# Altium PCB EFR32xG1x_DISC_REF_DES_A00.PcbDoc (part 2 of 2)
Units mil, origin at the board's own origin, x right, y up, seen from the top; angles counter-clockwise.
Board outline 1181.1 x 1771.65 mil, 4 copper layers (Top Layer, Signal Layer 2, Signal Layer 3, Bottom Layer), stack 63.229 mil thick; 88 components, 86 nets, 332 pads, 389 vias.
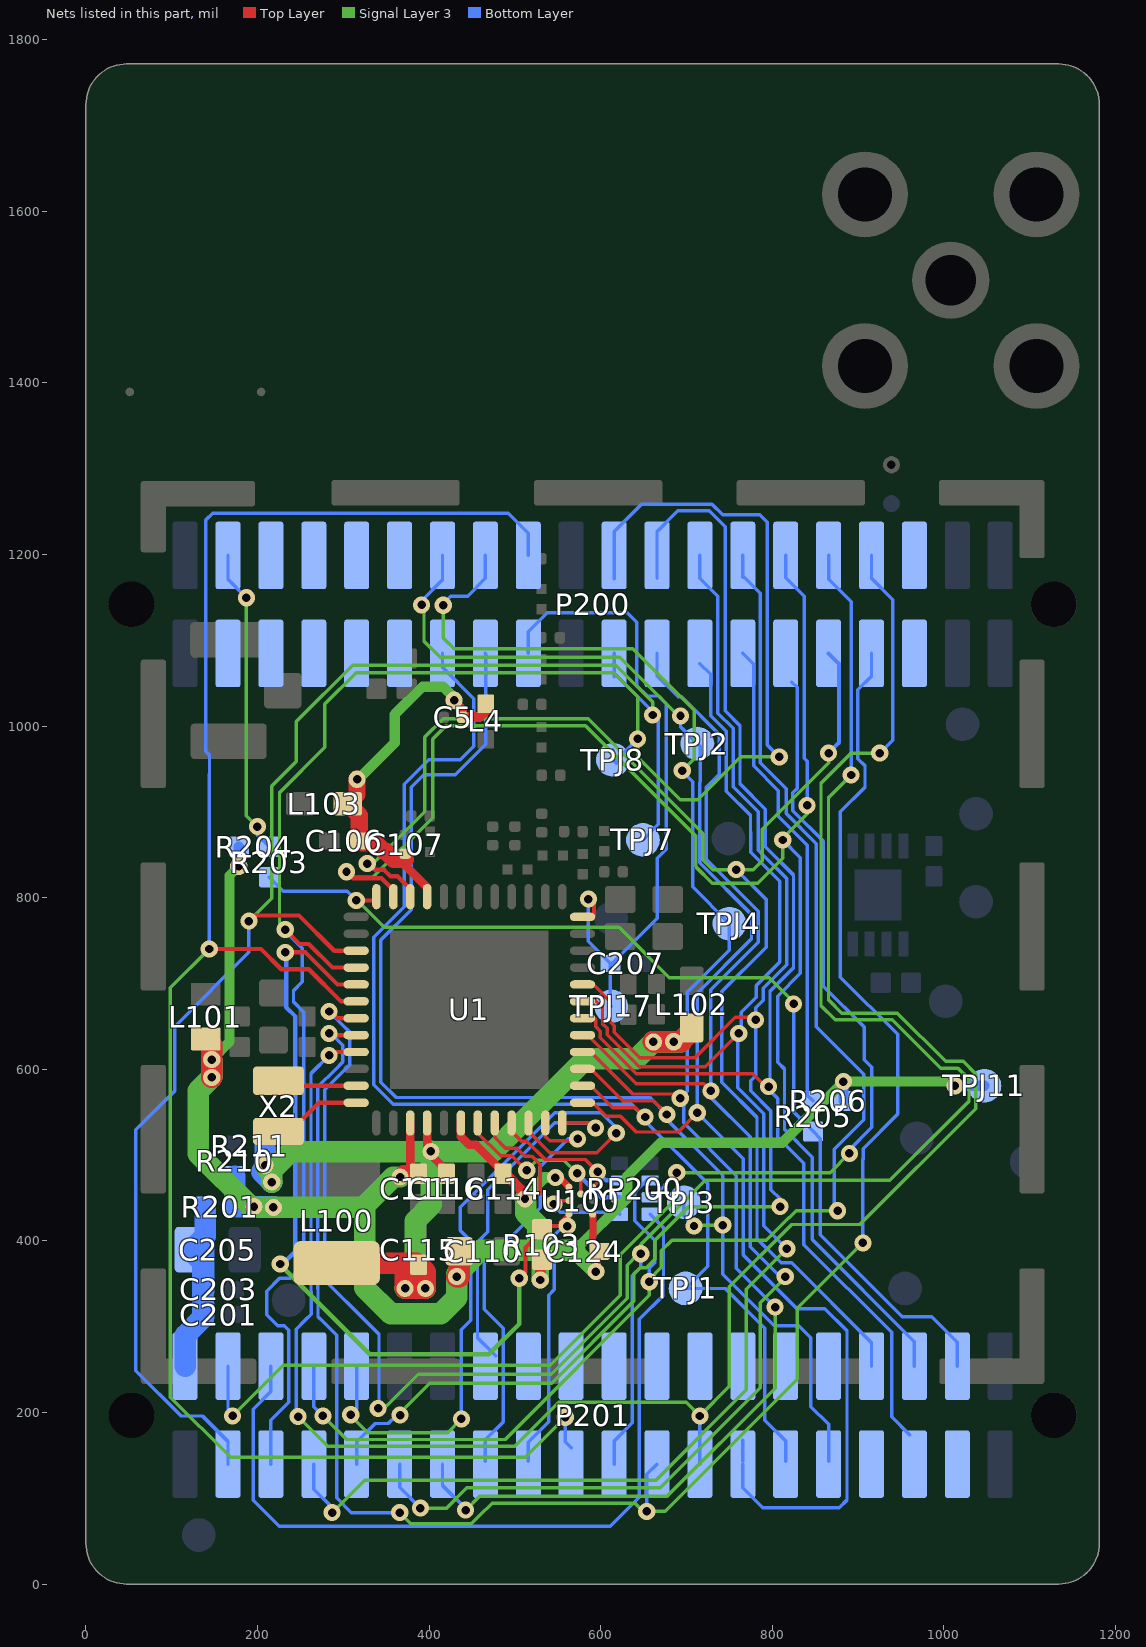
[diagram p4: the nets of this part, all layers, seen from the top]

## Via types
v1: diameter 20, hole 9.84, Top Layer to Bottom Layer, tented both sides, 385 vias
v2: diameter 19.68, hole 9.84, Top Layer to Bottom Layer, tented both sides, 2 vias
v3: diameter 20, hole 9.84, Top Layer to Bottom Layer, 2 vias

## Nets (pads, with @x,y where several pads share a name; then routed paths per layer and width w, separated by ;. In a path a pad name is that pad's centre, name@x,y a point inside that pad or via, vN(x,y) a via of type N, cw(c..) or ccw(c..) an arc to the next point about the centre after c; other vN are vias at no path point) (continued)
RADIO_PA2: P200.21 P201.3 TPJ7.1 U1.27 | length 1872.5
  Top Layer w5: v1(189.96,772.64) 196.62,779.3 248.26,779.3 289.37,738.19 U1.27@314.96,738.19
  Signal Layer 3 w4: v1(189.96,772.64) 216.54,799.21 216.54,930.12 245.08,958.66 245.08,1005.27 310.81,1071 617.48,1071 660.47,1028.01 v1(660.47,1012.84)
  Bottom Layer w4: P201.3@165.55,139.76 165.55,166.14 135.83,195.87 110.94,195.87 58.07,248.73 58.07,529.33 103.35,574.6 103.35,649.61 189.96,736.22 v1(189.96,772.64) ; P200.21@615.55,1057.68 P200.21@615.55,1061.61 ; P200.21@615.55,1084.65 P200.21@615.55,1061.61 ; TPJ7.1@649.21,867.32 657.73,875.84 657.48,876.1 667,885.62 667,1006.31 v1(660.47,1012.84) 660.47,1016.7 P200.21@615.55,1061.61
RADIO_PA3: P200.22 P201.5 TPJ8.1 U1.28 | length 2331
  Top Layer w5: v1(232.28,762.8) 249.02,746.06 259.76,746.06 287.32,718.5 U1.28@314.96,718.5
  Signal Layer 3 w4: v1(232.28,762.8) 225.59,769.48 225.59,922.44 278.54,975.39 278.54,1025.69 314.86,1062 615.17,1062 643,1034.17 v1(643,985) 643,963.69 692.69,914 713,914 763,964 v1(808,964)
  Bottom Layer w4: P201.5@215.55,139.76 215.55,191.13 236.12,211.7 236.12,287.4 ; v1@235.24,757.86 252.22,740.88 252.22,702.01 241.87,691.67 241.87,678.41 253.94,666.35 253.94,372.05 238.28,356.39 225.58,356.39 210.54,341.35 210.54,314.07 223.33,301.28 230.9,301.28 236.22,295.95 236.22,287.4 ; TPJ8.1@614.17,972.44 TPJ8.1@614.17,960.63 618.36,956.45 618.36,960.36 v1(643,985) ; P200.22@615.55,1171.85 P200.22@615.55,1198.82 615.55,1226.77 647.51,1258.73 729.64,1258.73 742.21,1246.16 785.34,1246.16 794.12,1237.38 794.12,977.88 v1(808,964)
RADIO_PA4: P201.17 R103.2 U1.29 U100.A3 | length 1280.2
  Top Layer w5: v1(232.28,736.22) 255.83,736.22 293.23,698.82 U1.29@314.96,698.82 ; v1(504.95,356.32) 512.41,363.78 512.41,392.33 531.5,411.42 R103.2@531.5,413.39 535.3,417.19 v1@557.14,417.19 ; v1(560.93,417.19) v1@557.14,417.19 ; U100.A3@562.91,431.1 553.07,421.26 v1@557.14,417.19
  Signal Layer 3 w5: v1(226.38,373.03) 226.38,372.05 330.71,267.72 469.5,267.72 504.95,303.16 v1(504.95,356.32)
  Bottom Layer w4: P201.17@515.55,143.11 515.55,165.16 539.37,188.98 539.37,253.47 ; 539.17,253.66 539.37,253.47 ; v1(560.93,417.19) 556.88,417.19 546.04,406.35 546.04,343.28 539.37,336.61 539.37,253.47
  Bottom Layer w5: v1@227.36,371.06 227.85,371.56 244.09,387.8 244.09,661.42 233.37,672.14 233.37,734.36 233.3,734.29 232.28,735.31 v1(232.28,736.22)
RADIO_PA5: P200.18 P201.19 U1.30 | length 2200.8
  Top Layer w5: v1(143.7,740.16) 204.07,740.16 227.7,716.54 259.76,716.54 297.17,679.13 U1.30@314.96,679.13
  Signal Layer 3 w4: v1(143.7,740.16) 98.43,694.88 98.43,217.85 168.63,147.64 511.81,147.64 v1(558.58,194.41)
  Bottom Layer w4: v1(143.7,740.16) 143.7,943.91 143.95,944.16 143.95,966.28 139.76,970.47 139.76,1240.16 147.64,1248.03 492.13,1248.03 515.55,1224.61 P200.18@515.55,1198.82 ; v1(558.58,194.41) 558.58,165.95 P201.19@565.55,158.98
RADIO_PB11: P200.34 P201.21 U1.31 | length 2490.7
  Top Layer w5: v1(283.39,667.32) 285.36,667.32 293.23,659.45 U1.31@314.96,659.45
  Signal Layer 3 w4: v1@344,201.28 387.3,244.59 542.08,244.59 630.78,333.29 630.78,371.78 643.86,384.86 v1(646.69,384.86) 646.69,395.7 721.54,470.55 937.01,470.55 1029.15,562.69 1029.15,588.58 1016.35,601.38 996.05,601.38 939.95,657.48 873.07,657.48 856.66,673.89 856.66,933.51 891.65,968.5 v1(925.2,968.5)
  Bottom Layer w4: v1(283.39,667.32) 299.39,651.32 299.47,651.32 307.39,643.4 307.39,605.13 278.54,576.28 278.54,354.24 303.6,329.18 303.69,329.18 341.54,291.34 341.54,205.71 v1(340.55,204.72) ; P201.21@615.55,139.76 615.55,166.73 636.81,187.99 636.81,359.25 646.69,369.13 v1(646.69,384.86) ; P200.34@915.55,1198.82 915.55,1172.09 940.21,1147.43 940.21,983.52 v1(925.2,968.5)
RADIO_PB12: P200.33 P201.23 U1.32 | length 2239.1
  Top Layer w5: v1(283.39,641.73) 285.35,639.76 U1.32@314.96,639.76
  Signal Layer 3 w4: v1(365.67,83.19) 378.68,70.14 449.08,70.14 453.74,74.8 458.44,79.51 473.3,94.36 639.89,94.36 653.54,80.71 v1(653.54,84.65) 675.2,84.65 829.23,238.68 829.23,321.36 v1(905.51,397.64)
  Bottom Layer w4: v1(283.39,641.73) v1@284.41,640.71 ; v1@285.43,641.73 285.61,641.73 299.39,627.95 299.39,608.44 291,600.05 270.29,579.35 270.29,344.39 270.42,344.26 270.42,311.76 277.3,304.87 292.19,289.98 292.19,100.44 309.44,83.19 v1(365.67,83.19) ; v1(653.54,84.65) 653.54,127.75 P201.23@665.55,139.76 ; v1(905.51,397.64) 905.51,495.09 905.76,495.34 905.76,507.56 946,547.79 946,640.61 879.2,707.42 879.2,899.86 907.99,928.65 907.99,953.74 899.73,962 899.73,1042.45 915.55,1058.27 P200.33@915.55,1084.65
RADIO_PB13: P200.32 P201.25 U1.33 | length 2362.4
  Top Layer w5: v1(283.39,616.14) 283.39,618.11 281.42,620.08 U1.33@314.96,620.08
  Signal Layer 3 w4: v1(247.31,195.1) 281.97,160.44 499.61,160.44 551.18,212.01 699.41,212.01 v1(715.55,195.87) 750,230.31 750,346.45 822.59,419.04 902.06,419.04 1037.15,554.13 1037.15,594.49 1022.26,609.38 1001.85,609.38 945.75,665.48 880.87,665.48 865.43,680.93 865.43,916.61 v1(891.73,942.91)
  Bottom Layer w4: v1@244.98,200.24 244.98,297.15 255.85,308.02 262.39,314.56 262.39,340.97 262.29,341.08 262.29,595.05 v1(283.39,616.14) ; P201.25@715.55,139.76 v1(715.55,195.87) ; P200.32@865.55,1198.82 865.55,1170.91 891.73,1144.73 v1(891.73,942.91)
RADIO_PB14: U1.35 X2.2 | length 93
  Top Layer w5: X2.2@224.33,586.61 230.24,580.71 U1.35@314.96,580.71
RADIO_PB15: U1.36 X2.1 | length 104.4
  Top Layer w5: X2.1@224.33,527.56 238.11,527.56 271.57,561.02 U1.36@314.96,561.02
RADIO_PC6: RP200.2 U1.43 U100.D2 | length 243.9
  Top Layer w4: U1.43@456.61,537.4 456.61,525.59 483.2,499 496.44,499 513.16,482.28 v1(513.7,482.28) ; v1(572.38,478.78) 576.69,474.46 U100.D2@576.69,454.72
  Signal Layer 3 w4: v1(513.7,482.28) 525.51,494.09 557.06,494.09 v1(572.38,478.78)
  Bottom Layer w5: v1(572.38,478.78) 600.37,450.79 RP200.2@622.05,450.79
RADIO_PC7: RP200.1 U1.44 U100.C3 | length 228.3
  Top Layer w4: U1.44@476.38,537.4 476.3,520.7 489,508 502,508 511.65,498.35 517.82,498.35 517.88,498.28 520.33,498.28 529.7,488.91 529.7,475.66 529.45,475.4 529.45,456.69 v1@537.32,448.82 ; v1(545.28,442.91) 549.21,446.85 U100.C3@562.91,446.85
  Bottom Layer w4: v1@544.25,441.89 552.95,433.19 619.96,433.19 RP200.1@622.05,431.1
RADIO_PC8: RP200.3 U1.45 U100.E1 | length 179.7
  Top Layer w4: U1.45@496.06,537.4 495.98,527.64 507.62,516 513.92,516 535.15,494.78 581.91,494.78 v1(596.38,480.31) 596.38,468.5 U100.E1@590.47,462.6
  Bottom Layer w5: v1(596.38,480.31) 606.22,470.47 RP200.3@622.05,470.47
RADIO_PC9: P201.10 U1.46 | length 831
  Top Layer w4: U1.46@515.75,537.4 515.75,527.56 540.53,502.78 595.22,502.78 v1(618.03,525.59)
  Signal Layer 3 w4: v1(308.58,197.36) 308.58,196.39 328.53,176.44 421.52,176.44 v1(437.52,192.44)
  Bottom Layer w4: v1(308.58,197.36) 315.55,204.33 P201.10@315.55,253.94 ; v1@437.52,194.26 437.52,296.58 448.32,307.38 448.32,400.11 436.38,412.05 436.38,439.33 546.26,549.21 600.39,549.21 618.03,531.57 v1(618.03,525.59)
RADIO_PC10: P201.15 U1.47 | length 501
  Top Layer w4: U1.47@535.43,537.4 535.43,521.57 540.36,516.64 570.88,516.64 v1(573.02,518.78)
  Bottom Layer w4: P201.15@465.55,143.11 465.55,168.31 486.12,188.87 486.12,298.33 464.32,320.13 464.32,373.76 529.28,438.72 529.28,475.23 529.7,475.66 529.7,486.39 562.09,518.78 v1(573.02,518.78)
RADIO_PC11: P201.16 U1.48 | length 409
  Top Layer w4: U1.48@555.04,537.4 U1.48@555.12,537.4 588.34,537.4 v1(594.03,531.71)
  Bottom Layer w4: P201.16@477.61,265.99 456.32,287.28 456.32,398.24 468.5,410.43 468.5,459.71 546.19,537.4 588.34,537.4 v1(594.03,531.71)
RADIO_PD13: P200.31 P201.34 U1.22 | length 1725.3
  Top Layer w5: v1(327.77,839.61) 329.62,839.61 336.88,832.35 347.53,832.35 354.87,825 363.03,825 377.87,810.16 U1.22@377.87,801.18
  Signal Layer 3 w4: v1(327.77,839.61) 334.47,839.61 395,900.14 395,987.21 416.29,1008.5 585.49,1008.5 719,875 719,844.41 730.73,832.68 v1(757.87,832.68) 777.6,832.68 788,843.08 788,879.66 865.55,957.21 v1(865.55,968.5)
  Bottom Layer w4: v1(757.87,832.68) 792.68,797.87 792.68,742.13 741.14,690.59 741.14,584.75 782.13,543.76 782.13,402.42 810.27,374.27 822.58,374.27 915.55,281.3 P201.34@915.55,253.94
  Bottom Layer w5: v1(865.55,968.5) 877.72,980.67 877.72,1072.48 P200.31@865.55,1084.65
RADIO_PD14: P200.30 P201.36 U1.23 | length 1893.4
  Top Layer w5: v1(303.68,830.18) 311.25,822.61 344.39,822.61 358.19,808.81 U1.23@358.27,801.18
  Signal Layer 3 w4: v1(303.68,830.18) 303.55,830.18 303.15,829.78 309.32,823.61 334.4,823.61 404,893.21 404,984.9 419.61,1000.5 582.18,1000.5 711,871.68 711,835.73 730.05,816.68 782.86,816.68 812.05,845.86 v1(812.05,867.17) 812.05,869.13 840.55,897.64 v1(840.55,907.48)
  Bottom Layer w4: v1(812.05,867.17) 832.68,846.54 832.68,711.76 806.1,685.18 806.1,608.27 814.13,600.24 814.13,529.88 846.46,497.55 846.46,401.57 965.55,282.48 P201.36@965.55,253.94 ; P200.30@815.55,1198.82 815.55,1172.9 836.98,1151.47 836.98,998.16 836.99,962.7 840.55,959.14 v1(840.55,907.48)
RADIO_PD15: P201.38 R203.1 R205.1 U1.24 | length 1220.3
  Top Layer w5: v1(314.96,796.78) 334.1,796.78 U1.24@338.5,801.18
  Signal Layer 3 w4: v1(314.96,796.78) 316.12,796.78 347.57,765.33 621.24,765.33 679.94,706.63 796.32,706.63 824.8,678.15 v1(824.8,676.18)
  Bottom Layer w4: R203.1@213.58,823.82 230.06,807.34 304.4,807.34 v1(314.96,796.78) ; v1(824.8,676.18) 824.8,550.2 R205.1@847.44,527.56 855.85,519.15 855.85,407.03 951.35,311.54 985.75,311.54 1015.55,281.73 P201.38@1015.55,253.94
RADIO_PF0: P200.14 P201.27 TPJ2.1 U1.1 | length 1856.4
  Top Layer w4: U1.1@578.66,561.02 U1.1@578.74,561.02 590.47,561.02 606.22,545.28 623,545.28 641.44,526.84 690.14,526.84 v1(712.52,549.21)
  Signal Layer 3 w4: v1@390,1141 394,1137 394,1099 413,1080 622,1080 690.19,1011.81 v1(692.91,1011.81)
  Bottom Layer w4: v1(391.26,1141.26) 391.26,1146.18 415.55,1170.47 P200.14@415.55,1198.82 ; v1(692.91,1011.81) 692.91,999.21 TPJ2.1@712.6,979.53 715.8,976.32 715.8,934.85 715.13,934.18 715.13,841.48 715.8,840.81 715.8,840.21 775.69,780.32 775.69,751.97 712.35,688.63 712.35,549.39 v1(712.52,549.21) 766.13,495.6 766.13,383.48 828.74,320.87 861.31,320.87 886.98,295.19 886.98,97.95 878.13,89.1 788.9,89.1 765.55,112.44 P201.27@765.55,139.76 ; P201.27@765.55,143.11 P201.27@765.55,167.52
RADIO_PF1: P200.13 P201.29 TPJ1.1 U1.2 | length 1524.2
  Top Layer w4: U1.2@578.74,580.71 588.5,580.71 614.09,555.12 640.83,555.12 v1(651.61,544.33)
  Bottom Layer w4: P200.13@415.55,1084.65 415.55,1068.45 452,1032 452,976.33 436.17,960.5 399.48,960.5 371.06,932.09 371.06,789.37 335.63,753.94 335.63,581.69 358.27,559.06 635.83,559.06 v1@651.57,543.31 ; v1@651.5,543.31 651.5,539.97 724.66,466.8 724.66,370.33 TPJ1.1@698.82,344.49 745.13,344.49 791.34,298.28 791.34,190.94 815.55,166.73 P201.29@815.55,143.11
RADIO_PF2: P200.15 P201.31 TPJ3.1 U1.3 | length 1607.1
  Top Layer w4: U1.3@578.74,600.39 588.5,600.39 625.78,563.12 661.32,563.12 v1(677.16,547.24)
  Signal Layer 3 w4: v1(708.66,417.32) 709.8,418.46 709.96,418.31 v1(742.13,418.31)
  Bottom Layer w4: P200.15@465.55,1084.65 466,1084.2 466,979.01 430.28,943.29 393.58,943.29 379.06,928.77 379.06,786.06 343.63,750.62 343.63,585.01 361.58,567.06 657.35,567.06 659.45,564.96 v1(677.16,547.24) 677.16,541.35 742.13,476.39 v1(742.13,418.31) 742.13,361.23 802.08,301.28 830.9,301.28 844.98,287.19 844.98,206.6 865.55,186.03 P201.31@865.55,143.11 ; TPJ3.1@696.85,444.88 696.85,429.13 v1(708.66,417.32)
RADIO_PF3: P200.16 P201.13 TPJ4.1 U1.4 | length 1964.2
  Top Layer w4: U1.4@578.66,620.08 U1.4@578.74,620.08 588.5,620.08 637.46,571.12 687.65,571.12 v1(692.64,566.12)
  Signal Layer 3 w4: v1@416.36,1140.64 416.36,1102.64 429,1090 637.35,1090 708.91,1018.44 708.91,961.91 v1(695,948) ; v1(442.44,86.14) 458.66,102.36 677.17,102.36 803.15,228.34 v1(803.15,322.83)
  Bottom Layer w4: P201.13@415.55,139.76 415.55,114.89 442.44,88 v1(442.44,86.14) ; v1(416.36,1140.8) 416.36,1142.74 425.1,1151.48 444.79,1151.48 465.55,1172.24 P200.16@465.55,1198.82 ; v1(695,948) 695,947.36 707.13,935.22 707.13,812.55 TPJ4.1@750,769.68 750,738.92 701.04,689.96 701.04,574.52 v1(692.64,566.12) 696.52,562.25 696.52,537.4 758.13,475.79 758.13,367.86 v1(803.15,322.83)
RADIO_PF4: P200.23 P201.11 U1.5 | length 1687.3
  Top Layer w4: U1.5@578.66,639.76 U1.5@578.74,639.76 584.65,639.76 641.16,583.25 719.9,583.25 v1(728.35,574.8)
  Signal Layer 3 w4: v1(389.76,88.58) 420.28,88.58 443.9,112.2 669.29,112.2 785.69,228.61 785.69,328.01 815.95,358.27 v1(814.96,358.27)
  Bottom Layer w4: P201.11@365.55,139.76 365.55,112.8 v1(389.76,88.58) ; P200.23@665.55,1084.65 665.55,1058.86 690.19,1034.22 694.23,1034.22 738.28,990.17 738.28,943.68 723.13,928.53 723.13,844.79 783.69,784.24 783.69,748.03 728.35,692.69 v1(728.35,574.8) ; v1@728.52,574.8 728.52,566.93 774.13,521.32 774.13,393.2 809.06,358.27 v1(814.96,358.27)
RADIO_PF5: P200.24 P201.35 U1.6 | length 1579.2
  Top Layer w4: U1.6@582.68,661.42 590.58,661.42 594,658 594,649.79 599.5,644.29 599.5,636.72 641.53,594.69 777.35,594.69 792.27,579.78 v1(795.62,579.78)
  Bottom Layer w4: P200.24@665.55,1172.09 P200.24@665.55,1198.82 665.55,1226.57 689.71,1250.73 726.32,1250.73 744.98,1232.07 744.98,1017.8 762.28,1000.5 762.28,932.59 791.69,903.19 791.69,859.39 824.68,826.4 824.68,718.38 797.28,690.98 797.28,581.44 v1(795.62,579.78) 795.62,576.43 806.13,565.92 806.13,520.67 836.5,490.29 836.5,395.67 938.92,293.25 938.92,194.98 P201.35@960.16,173.74
RADIO_PF6: P200.25 P201.7 U1.7 | length 1801.9
  Top Layer w4: U1.7@578.66,679.13 U1.7@578.74,679.13 594.87,679.13 602,672 602,653.11 607.5,647.6 607.5,640.03 644.84,602.69 721.79,602.69 v1(760.83,641.73)
  Signal Layer 3 w4: v1(286.81,83.19) 324.69,121.06 664.37,121.06 769.69,226.38 769.69,343.5 v1(816.93,390.75)
  Bottom Layer w4: P201.7@265.55,139.76 265.55,110.43 286.81,89.17 v1(286.81,83.19) ; P200.25@715.55,1072.83 728.12,1060.27 728.12,1012.04 746.28,993.87 746.28,924.02 774.5,895.8 774.5,876.09 774.61,875.98 774.61,853.09 808.68,819.02 808.68,725.01 781.28,697.61 781.28,683.85 763.78,666.35 763.78,644.68 v1(760.83,641.73) 759.46,640.37 759.46,578.64 790.13,547.98 790.13,417.55 v1(816.93,390.75)
RADIO_PF7: P200.26 P201.9 U1.8 | length 1777.6
  Top Layer w4: v1@364.17,198.82 v1(366.14,196.85) ; U1.8@578.74,698.82 591.18,698.82 610,680 610,656.42 615.5,650.91 615.5,643.34 645.46,613.39 709.86,613.39 756.9,660.43 777.56,660.43 v1(780.51,657.48)
  Signal Layer 3 w4: v1(366.14,196.85) 366.14,199.63 400.77,234.25 543.06,234.25 638.78,329.98 638.78,361.69 645.95,368.86 653.31,368.86 662.69,378.23 662.69,400.39 702.26,439.96 v1(809.06,439.96)
  Bottom Layer w4: P201.9@315.55,139.76 315.55,165.69 336.96,187.1 352.46,187.1 362.2,196.85 v1(366.14,196.85) ; P200.26@715.55,1198.82 715.55,1172.28 736.47,1151.36 736.47,1015 754.28,997.19 754.28,929.27 783.69,899.87 783.69,855.33 816.68,822.34 816.68,721.69 789.28,694.3 789.28,680.54 780.51,671.77 v1(780.51,657.48) 780.51,592.52 774.61,586.61 774.61,574.81 798.13,551.29 798.13,459.75 809.06,448.82 v1(809.06,439.96)
USB_VBUS: P200.35
USB_VREG: P200.36
VBIAS: C5.1 C106.1 C107.1 L4.1 L103.2 U1.21 | length 436.9
  Top Layer w8: C5.1@438,1010.65 C5.1@438.65,1010 C5.1@438.82,1010.17 ; C5.1@439,1010 439.17,1010.17 C5.1@439.64,1010.64
  Top Layer w10: 369.55,840.02 397.56,812.01 U1.21@397.56,801.18
  Top Layer w12: v1(429,1030) 429,1028 438,1019 C5.1@438,1010.65 ; C5.1@438.82,1010.17 C5.1@439.17,1010.17 ; C5.1@439.64,1010.64 458.64,1010.64 466,1018 L4.1@466,1026
  Top Layer w20: v1(315.94,937.99) 315.94,920.28 L103.2@305.12,909.45 318.52,896.05 318.52,866.52 C106.1@318.9,866.14 321.43,863.61 337.71,863.61 347.21,854.11 349.1,854.11 358.72,844.49 372.05,844.49
  Signal Layer 3 w12: v1@317.57,937.98 360,980.4 360,1013.54 392.23,1045.77 416.23,1045.77 v1@428,1034
VDCDC: C115.1 C116.1 L100.2 L102.1 R211.2 U1.40 | length 1146.8
  Top Layer w10: U1.40@397.56,537.4 v1@397.56,504.78 ; v1(401.96,504.16) 401.34,504.78 v1@397.56,504.78 ; C116.1@420.28,478.35 420.28,482.06 v1@397.56,504.78
  Top Layer w25: L100.2@291.26,374.02 C115.1@385.75,374.02 ; v1(661.42,631.89) v1@693,631.89 ; v1(685,632) 692.95,632 706,645.05 L102.1@706,648 ; C115.1@385.75,374.02 395.59,364.17 v1(395.59,344.49) v1(371.97,344.49) 371.97,360.24 C115.1@385.75,374.02
  Signal Layer 3 w25: v1(208.72,488.19) v1@216.54,476.38 ; v1(216.54,468.5) v1@216.54,476.38 ; v1@393.82,346.26 383.78,356.3 ; v1(395.59,344.49) v1(371.97,344.49) 383.78,356.3 ; v1@402.56,504.16 v1@402.56,503.94 ; v1@694.04,631.89 v1(661.42,631.89) 641.73,612.2 582.6,612.2 509.76,539.37 474.33,503.94 v1@402.56,503.94 ; v1@216.54,476.38 216.54,482.28 238.19,503.94 v1@402.56,503.94 ; 383.78,356.3 383.78,423.15 402.56,441.93 v1@402.56,503.94
  Bottom Layer w25: R211.2@208.66,510.83 208.72,506.89 v1(208.72,488.19) 204.72,480.31 v1(216.54,468.5)
VMCU: C110.1 C111.1 C114.1 C124.1 L101.1 R103.1 R201.2 R204.1 R206.1 R210.2 TPJ11.1 U1.39 U1.42 U100.A1 U100.E3 | length 2324.7
  Top Layer w8: v1(547.17,473.78) 551.73,473.78 U100.E3@562.91,462.6 ; U100.A1@590.47,431.1 590.93,430.65 590.93,404.76 590.47,404.31 590.47,391.73 C124.1@594.41,387.8
  Top Layer w10: U1.39@377.87,537.4 377.87,488.19 C111.1@387.72,478.35 ; U1.42@436.93,537.4 436.93,521.65 446.77,511.81 454.65,511.81 C114.1@486.14,480.31
  Top Layer w12: C114.1@486.14,480.31 511.73,454.73 v1(511.73,448.82) ; v1(529.53,354.33) 529.53,375.98 R103.1@531.5,377.95 ; v1(594.41,364.17) C124.1@594.41,387.8
  Top Layer w20: v1(366.06,474.41) 370,478.35 C111.1@387.72,478.35
  Top Layer w25: L101.1@139.76,635.24 146.65,628.35 v1(146.65,611.22) v1(146.65,590.55) ; v1(432.11,358.29) 435.02,358.29 C110.1@435.04,387.8
  Signal Layer 3 w12: v1(146.65,611.22) 167.32,631.89 167.32,825.79 v1(178.15,836.61) ; 527.56,388.78 529.53,386.81 ; 569.8,388.78 630.89,449.86 630.89,475.37 669.73,514.22 811.46,514.22 v1(882.87,585.63) 1007.87,585.63 v1(1012.8,580.71)
  Signal Layer 3 w13: v1(511.73,448.82) 511.73,451.32 534.19,473.78 v1(547.17,473.78)
  Signal Layer 3 w20: v1(529.53,354.33) 529.53,386.81 ; 569.8,388.78 v1(594.41,364.17)
  Signal Layer 3 w25: v1(146.65,611.22) v1(146.65,590.55) 130.91,574.8 130.91,501.31 192.26,439.96 v1(195.87,439.96) 196.85,438.98 v1(218.5,438.98) 322.68,438.98 324.72,441.02 ; v1(366.06,474.41) 358.11,474.41 324.72,441.02 ; v1(511.73,448.82) 512.64,447.91 512.64,432.16 526.57,418.23 526.57,402.41 527.56,401.42 527.56,388.78 ; 569.8,388.78 527.56,388.78 ; 324.72,441.02 324.72,345.47 355.24,314.96 413.39,314.96 432.11,333.68 v1(432.11,358.29) 432.11,361.24 459.65,388.78 527.56,388.78
  Bottom Layer w12: v1(178.15,836.61) R204.1@178.15,859.25 ; R206.1@882.87,562.99 v1(882.87,585.63) ; v1(1012.8,580.71) TPJ11.1@1047.24,580.71
  Bottom Layer w25: R210.2@173.23,475.39 173.23,440.94 R201.2@174.21,439.96 v1(195.87,439.96) ; v1@199.73,439.96 v1(195.87,439.96) ; v1(218.5,438.98) 217.98,439.5 195.87,439.5 v1(195.87,439.96)
VMCU_IN: C201.1 C203.1 C205.1 P201.2 R201.1 | length 285.6
  Bottom Layer w25: P201.2@115.55,253.94 115.55,289.76 C201.1@137.32,311.54 ; 137.32,325.79 C201.1@137.32,311.54 ; C205.1@137.8,403.54 137.32,403.07 137.32,342.05 C203.1@136.34,341.06 ; R201.1@138.78,439.96 138.78,405.51 122.05,388.78 136.34,374.49 C203.1@136.34,341.06 ; C203.1@136.34,341.06 136.34,312.52 C201.1@137.32,311.54
WSTK_F4: C207.1 P200.17 TPJ17.1 U1.12 | length 785.8
  Top Layer w5: U1.12@578.66,777.56 U1.12@578.74,777.64 ; U1.12@578.74,777.56 591.56,777.56 592,778 592,791.93 v1(585.66,798.27)
  Bottom Layer w4: P200.17@515.55,1084.65 515.55,1110.04 537.5,1131.98 630.9,1131.98 642.11,1120.77 642.11,1046.87 653.98,1035 667.51,1035 676.47,1026.04 676.47,856.17 665.96,845.66 665.96,776.2 613.19,723.43 C207.1@611.22,723.43 ; v1(585.66,798.27) 585.66,748.99 C207.1@611.22,723.43 ; TPJ17.1@612.2,673.23 611.22,674.21 C207.1@611.22,723.43
WSTK_F14: P200.27 R205.2 R206.2 | length 555.6
  Bottom Layer w4: P200.27@765.55,1084.65 778.12,1072.08 778.12,953.68 807.09,924.71 807.09,894.76 840.68,861.17 840.68,685.17 840.8,685.04 840.8,569.63 R205.2@847.44,562.99
WSTK_F15: P200.28 P201.8 RP200.6 | length 1785.7
  Signal Layer 3 w4: v1(276.19,196.01) 303.76,168.44 488.56,168.44 656.53,336.41 v1(656.53,352.38) 656.53,354.87 670.69,369.03 670.69,388.2 683.07,400.59 792.82,400.59 819.27,427.04 819.75,427.04 827.75,435.04 v1(875.98,435.04)
  Bottom Layer w4: P201.8@265.55,253.94 265.55,206.65 v1(276.19,196.01) ; v1(656.53,352.38) 656.53,368.14 662.69,374.3 662.69,400.62 639.76,423.54 639.76,456.61 653.62,470.47 RP200.6@657.48,470.47 ; P200.28@765.55,1173.47 P200.28@765.55,1175.39 ; P200.28@765.55,1198.82 P200.28@765.55,1175.39 ; v1(875.98,435.04) 872.05,438.97 872.05,506.88 906.5,541.33 906.5,594.36 851.38,649.48 851.38,862.71 816.01,898.08 816.01,927.1 786.12,956.99 786.12,1154.83 P200.28@765.55,1175.39
WSTK_F16: P200.29 P201.4 RP200.7 | length 1597.5
  Signal Layer 3 w4: v1(170.87,196.01) 230.05,255.19 541.37,255.19 622.78,336.6 622.78,383.58 688.61,449.42 v1(688.61,479.49) 867.29,479.49 v1(889.76,501.97)
  Bottom Layer w4: P201.4@165.55,253.94 165.55,201.33 v1(170.87,196.01) ; RP200.7@657.48,450.79 661.34,450.79 674.68,464.14 674.68,465.56 v1(688.61,479.49) ; P200.29@822.83,1051.18 828.98,1045.03 828.98,994.85 ; 828.99,994.84 828.99,927.23 824.01,922.24 824.01,901.4 859.38,866.03 859.38,696.82 907,649.2 907,611.26 916,602.26 916,532.14 889.76,505.91 v1(889.76,501.97)
WSTK_P3: P201.6 RP200.8 | length 989.7
  Bottom Layer w4: P201.6@215.55,253.94 215.55,224.41 194.98,203.84 194.98,97.65 225.44,67.19 611.22,67.19 644.98,100.95 644.98,308.37 673.13,336.52 673.13,415.45 RP200.8@657.48,431.1
WSTK_P15: P201.18
WSTK_P17: P201.20
WSTK_P19: P201.22
WSTK_P21: P201.24
WSTK_P23: P201.26
WSTK_P25: P201.28
WSTK_P27: P201.30
WSTK_P29: P201.32
WSTK_P30: P201.33
WSTK_P34: P201.37
WSTK_P36: P200.3
WSTK_P37: P200.4 R203.2 R204.2 | length 359.5
  Signal Layer 3 w4: v1(187.01,1149.61) 187.01,895.67 v1(199.8,882.87)
  Bottom Layer w4: P200.4@165.55,1198.82 165.55,1171.06 v1(187.01,1149.61) ; v1(199.8,882.87) 199.8,873.03 R204.2@213.58,859.25
WSTK_P38: P200.5
WSTK_P39: P200.6
WSTK_P40: P200.7
WSTK_P41: P200.8
WSTK_P42: P200.9
WSTK_P43: P200.10
WSTK_P44: P200.11
WSTK_P45: P200.12
pads on no net: P200.M1 P200.M2 P201.40 P201.M1 P201.M2 RP200.4 RP200.5 TPJ9.1 TPJ18.1 TPJ19.1 TPJ20.1 U1.49@401.57,624.02 U1.49@401.57,714.57 U1.49@492.13,624.02 U1.49@492.13,714.57 U100.C1 U200.9

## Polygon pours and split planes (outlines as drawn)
GND on Signal Layer 2 "GND_L2" (solid, remove dead copper, pour order 27): 24,1365 826.55,1365 ccw(c826.55,1399.14) 860.69,1399.14 860.69,1597.28 931.56,1668.15 1085.1,1668.15 1155.97,1597.28 1155.89,46.7 cw(c1133.64,46.7) 1133.64,24.45 49.59,24.66 cw(c49.59,50.25) 24,50.25
GND on Bottom Layer "GND_L4" (solid, remove dead copper, pour order 24): 24,1365 826.55,1365 ccw(c826.55,1399.14) 860.69,1399.14 860.69,1597.28 931.56,1668.15 1085.1,1668.15 1155.97,1597.28 1155.89,46.7 cw(c1133.64,46.7) 1133.64,24.45 49.59,24.66 cw(c49.59,50.25) 24,50.25
GND on Signal Layer 3 "GND_L3" (solid, remove dead copper, pour order 25): 24,1365 826.55,1365 ccw(c826.55,1399.14) 860.69,1399.14 860.69,1597.28 931.56,1668.15 1085.1,1668.15 1155.97,1597.28 1155.89,46.7 cw(c1133.64,46.7) 1133.64,24.45 49.59,24.66 cw(c49.59,50.25) 24,50.25
GND on Top Layer "GND_L1" (solid, remove dead copper, pour order 29): 24,1365 826.55,1365 ccw(c826.55,1399.14) 860.69,1399.14 860.69,1597.28 931.56,1668.15 1085.1,1668.15 1155.97,1597.28 1155.89,46.7 cw(c1133.64,46.7) 1133.64,24.45 49.59,24.66 cw(c49.59,50.25) 24,50.25

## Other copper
Top Layer:
  pour cut-out: 511,935 597,935 619.96,912.04 620.15,862.89 619,860.38 619,817.28 581,790 571.81,790 556,774.18 556,564 546,553 408,553 404,549 404,429 400,425 323,425 319,429 319,854.55 330.59,866.14 451,866.14 451,912.62 476.57,935
Signal Layer 2:
  pour cut-out: 477.54,935 597,935 619.85,912.15 620.02,864.05 619,861.6 619,818.31 596.47,800 573,780 486.02,780 481.65,784.99 480.28,812.44 451,835.14 451,913.14
  region net GND: 439,932
  region net GND: 439,932
  pour cut-out: 119.95,1075.03 119.95,1008.1 201.92,1008.1 201.92,1018.67 252.95,1018.7 252.95,1064.7 201.95,1064.7 201.95,1075
Signal Layer 3:
  pour cut-out: 477.36,935 597,935 619.85,912.15 620.02,864.05 619,861.6 619,818.09 607,809 573,780 486.38,780 481.57,785.49 480.23,812.48 451,835.14 451,913.29
  pour cut-out: 595,948
  pour cut-out: 499,935
  pour cut-out: 439,944
Bottom Layer:
  pour cut-out: 938.78,1336.02 cw(c938.78,1304.53) 970.28,1304.53 cw(c938.78,1304.53) 938.78,1273.03 cw(c938.78,1304.53) 907.28,1304.53 cw(c938.78,1304.53)

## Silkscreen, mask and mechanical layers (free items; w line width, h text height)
Top Overlay:
  text "EFR32xG1x_DISC_REF_DES" at 3,1625 h68
  text "2.4GHz/Sub-GHz" at 39,1544 h74.8
  text "SubG match Layout  3" at 39,1465 h74.8
  text "EFR32FG14" at 388,88 h74.8
Bottom Overlay:
  lines w6: 155.51,469.49 155.51,457.68 167.32,457.68 ; 155.51,518.7 155.51,530.51 167.32,530.51 ; 160.43,852.36 160.43,840.55 172.24,840.55 ; 160.43,866.14 160.43,877.95 172.24,877.95 ; 181.1,457.68 192.91,457.68 192.91,469.49 ; 182.09,840.55 193.9,840.55 193.9,828.74 ; 192.91,479.33 192.91,491.14 204.72,491.14 ; 193.9,816.93 193.9,804.13 205.71,804.13 ; 216.54,491.14 229.33,491.14 229.33,502.95 ; 216.54,530.51 229.33,530.51 229.33,518.7 ; 221.46,804.13 233.27,804.13 233.27,816.93 ; 221.46,877.95 233.27,877.95 233.27,866.14 ; 829.72,521.65 829.72,509.84 841.54,509.84 ; 829.72,570.87 829.72,582.68 841.54,582.68 ; 855.32,509.84 867.13,509.84 867.13,521.65 ; 867.13,531.5 867.13,543.31 878.94,543.31 ; 890.75,543.31 903.54,543.31 903.54,555.12 ; 890.75,582.68 903.54,582.68 903.54,570.87
  text "BOARD  INFO" at 809.06,1706.69 h62.99
  text "EFR32xG1x_DISC_REF_DES_A00" at 874,1507 h60
  text "Sensor Enable" at 375.98,898.62 h62.99
  text "ON" at 149.61,845.47 h47.24
  text "PD15" at 342.52,839.57 h47.24
  text "Disp Enable" at 995.08,595.47 h62.99
  text "ON" at 968.5,549.21 h47.24
  text "PAVDD" at 259.84,545.28 h62.99
  text "PD15" at 815,535 h47.24
  text "VDCDC" at 377.95,496.06 h47.24
  text "VMCU" at 150.59,490.16 h47.24
Top Solder:
  the board outline again, w39.37
Bottom Solder:
  the board outline again, w39.37
BOARD OUTLINE 1:
  the board outline again, w3.94
Mechanical 2:
  lines w3.94: -19.68,0 19.69,0 ; 0,-19.69 0,19.68
Mechanical 11:
  the board outline again, w3.94
Mechanical 12:
  the board outline again, w3.94
EXT_SILKP 20:
  lines w6: 155.51,469.49 155.51,457.68 167.32,457.68 ; 155.51,518.7 155.51,530.51 167.32,530.51 ; 160.43,852.36 160.43,840.55 172.24,840.55 ; 160.43,866.14 160.43,877.95 172.24,877.95 ; 181.1,457.68 192.91,457.68 192.91,469.49 ; 182.09,840.55 193.9,840.55 193.9,828.74 ; 192.91,479.33 192.91,491.14 204.72,491.14 ; 193.9,816.93 193.9,804.13 205.71,804.13 ; 216.54,491.14 229.33,491.14 229.33,502.95 ; 216.54,530.51 229.33,530.51 229.33,518.7 ; 221.46,804.13 233.27,804.13 233.27,816.93 ; 221.46,877.95 233.27,877.95 233.27,866.14 ; 829.72,521.65 829.72,509.84 841.54,509.84 ; 829.72,570.87 829.72,582.68 841.54,582.68 ; 855.31,509.84 867.13,509.84 867.13,521.65 ; 867.13,531.5 867.13,543.31 878.94,543.31 ; 890.75,543.31 903.54,543.31 903.54,555.12 ; 890.75,582.68 903.54,582.68 903.54,570.87
  lines w6.06: 59.06,1496.06 59.06,1456.69 98.43,1456.69 ; 59.06,1653.54 59.06,1692.91 98.43,1692.91 ; 767.72,1456.69 807.09,1456.69 807.09,1496.06 ; 767.72,1692.91 807.09,1692.91 807.09,1653.54
  text "BOARD INFO" at 809.06,1706.69 h60
  text "Sensor Enable" at 372.05,899.61 h60
  text "ON" at 149.61,845.47 h45
  text "WSTK_P37" at 451.77,827.76 h45
  text "Disp Enable" at 995.08,595.47 h60
  text "ON" at 968.5,549.21 h45
  text "PAVDD" at 269.68,547.24 h60
  text "WSTK_P35" at 824.8,530.51 h45
  text "VDCDC" at 377.95,496.06 h45
  text "VMCU" at 150.59,478.35 h45
Mechanical 26:
  lines w7.87: -4937.2,-1888.27 -4740.35,-1888.27 ; -4937.2,-37.87 -4740.35,-37.87 ; -4936.72,1812.52 -4740.35,1812.52 ; -2133.75,-3739.9 -2133.75,-3543.05 ; -2133.75,3543.57 -2133.75,3740.42 ; 673.33,-3739.9 673.33,-3543.05 ; 673.33,3543.57 673.33,3740.42 ; 3476.48,-3739.9 3476.48,-3543.05 ; 3476.48,3543.57 3476.48,3740.42 ; 6086.43,-1888.27 6283.28,-1888.27 ; 6086.43,-37.87 6283.28,-37.87 ; 6086.43,1812.52 6282.8,1812.52 ; -4936.72,-3739.9 6283.28,-3739.9 6283.28,3740.1 -4936.72,3740.1 -4936.72,-3739.9 ; -4740.35,-3543.05 6086.43,-3543.05 6086.43,3543.57 -4740.35,3543.57 -4740.35,-3543.05
  text "1" at -3641.91,3605.44 h60
  text "2" at -795.17,3605.44 h60
  text "3" at 2063.1,3605.44 h60
  text "4" at 4850.5,3605.44 h60
  text "D" at 6165.09,2851.89 h60
  text "D" at -4862.91,2804.44 h60
  text "C" at -4862.91,934.57 h60
  text "C" at 6160.09,934.57 h60
  text "B" at -4862.91,-939.45 h60
  text "B" at 6160.09,-939.45 h60
  text "A" at -4862.91,-2809.53 h60
  text "A" at 6160.09,-2809.53 h60
  text "1" at -3593.91,-3678.56 h60
  text "2" at -795.17,-3678.56 h60
  text "3" at 2051.28,-3678.56 h60
  text "4" at 4834.75,-3678.56 h60
Mechanical 27:
  circle w10: c1520.59,-3267.52 r116.62
  circle w6: c2779.83,-2698.37 r70
  circle w6: c2779.83,-2698.37 r30
  lines w6: 2346.83,-2698.37 2636.83,-2698.37 ; 2689.83,-2698.37 2869.83,-2698.37 ; 2376.83,-2728.37 2376.83,-2668.37 2606.83,-2628.37 2605.83,-2768.37 2376.83,-2728.37
  lines w7.87: 1361.21,-3540.52 1361.21,-2483.05 2936.56,-2483.05 ; 1361.21,-2980.52 6084.21,-2980.52 ; 1361.76,-2837.38 2936.56,-2837.38 ; 2160.21,-3538.52 2160.21,-2983.52 ; 2160.21,-2835.52 2160.21,-2484.52 ; 5298.76,-2979.52 5298.76,-2837.38 ; 5692.47,-2837.38 5692.47,-2483.05 ; 6086.17,-2837.38 2936.56,-2837.38 ; 6086.17,-2483.05 2936.56,-2483.05 ; 2936.56,-2837.38 2936.56,-2483.05
  text "SIZE" at 1440.5,-2561.79 h60
  text "DOC NO" at 3015.3,-2561.79 h60
  text "REV" at 5771.21,-2561.79 h60
  text "PROJECTION" at 2200.21,-2575.52 h60
  text "'.ProjectRevision'" at 5760.21,-2755.52 h100
  text "A4" at 1544.83,-2773.37 h100
  text "xxxx" at 3113.71,-2773.37 h100
  text "REF" at 1440.5,-2916.12 h60
  text "SHEET" at 5338.13,-2916.12 h60
  text "1 of 2" at 5725.6,-2956.95 h60
  text "This drawing is confidential and is supplied on the express" at 2179.21,-3097.52 h60
  text "condition that it shall not be loaned, copied or disclosed to any" at 2179.21,-3197.52 h60
  text "other person or used for any purpose without the written consent of" at 2179.21,-3297.52 h60
  text "C" at 1497.21,-3307.52 h80
  text "2017" at 1697.21,-3313.52 h100
  text "SILICON LABS" at 2196.21,-3466.52 h100
Mechanical 28:
  lines w7.87: -4937.15,-1888.32 -4740.3,-1888.32 ; -4937.15,-37.92 -4740.3,-37.92 ; -4936.68,1812.47 -4740.3,1812.47 ; 6086.47,-1888.32 6283.32,-1888.32 ; 6086.47,1812.47 6283.32,1812.47
  lines w8: -4741.3,-3543.09 -4741.3,3543.52 ; -4740.3,-3543.09 6086.47,-3543.09 6086.47,3543.52 -4740.3,3543.52 ; -2133.71,-3739.95 -2133.71,-3543.09 ; -2133.71,3543.52 -2133.71,3740.37 ; 673.38,-3739.95 673.38,-3543.09 ; 673.38,3543.52 673.38,3740.37 ; 3476.53,-3739.95 3476.53,-3543.09 ; 3476.53,3543.52 3476.53,3740.37 ; -4936.68,-3739.95 6283.32,-3739.95 6283.32,3740.05 -4936.68,3740.05 -4936.68,-3739.95
  text "4" at -3601.87,3605.39 h60
  text "3" at -755.13,3605.39 h60
  text "2" at 2103.14,3605.39 h60
  text "1" at 4890.54,3605.39 h60
  text "D" at 6205.13,2851.84 h60
  text "D" at -4822.87,2804.39 h60
  text "C" at -4822.87,934.52 h60
  text "C" at 6205.13,871.53 h60
  text "B" at -4822.87,-939.5 h60
  text "B" at 6205.13,-982.8 h60
  text "A" at 6165.04,-2806.57 h60
  text "A" at -4822.87,-2809.57 h60
  text "A" at 6200.13,-2809.57 h60
  text "4" at -3553.87,-3678.61 h60
  text "3" at -755.13,-3678.61 h60
  text "2" at 2085.33,-3678.61 h60
  text "1" at 4874.8,-3678.61 h60
Mechanical 29:
  circle w10: c-167.95,-3270.05 r116.62
  circle w6: c-1427.2,-2700.9 r70
  circle w6: c-1427.2,-2700.9 r30
  lines w6: -1517.2,-2700.9 -1337.2,-2700.9 ; -1284.2,-2700.9 -994.2,-2700.9 ; -1254.2,-2630.9 -1024.2,-2670.9 -1024.2,-2730.9 -1253.2,-2770.9 -1254.2,-2630.9
  lines w7.87: -4733.53,-2839.91 -1583.93,-2839.91 ; -4733.53,-2485.58 -1583.93,-2485.58 ; -4731.57,-2983.05 -8.57,-2983.05 ; -4339.83,-2839.91 -4339.83,-2485.58 ; -3946.13,-2982.05 -3946.13,-2839.91 ; -807.57,-3541.05 -807.57,-2986.05 ; -807.57,-2838.05 -807.57,-2487.05 ; -9.12,-2839.91 -1583.93,-2839.91 ; -9.12,-2485.58 -1583.93,-2485.58 ; -8.57,-3543.05 -8.57,-2483.05 ; -1583.93,-2839.91 -1583.93,-2485.58
  text "REV" at -4418.57,-2564.32 h60
  text "DOC NO" at -1662.67,-2564.32 h60
  text "SIZE" at -87.87,-2564.32 h60
  text "PROJECTION" at -847.57,-2578.05 h60
  text "'.ProjectRevision'" at -4407.57,-2758.05 h100
  text "xxxx" at -1761.08,-2775.9 h100
  text "A4" at -192.2,-2775.9 h100
  text "SHEET" at -3985.5,-2918.65 h60
  text "REF" at -87.87,-2918.65 h60
  text "2 of 2" at -4366.92,-2956.95 h60
  text "This drawing is confidential and is supplied on the express" at -826.57,-3100.05 h60
  text "condition that it shall not be loaned, copied or disclosed to any" at -826.57,-3200.05 h60
  text "other person or used for any purpose without the written consent of" at -826.57,-3300.05 h60
  text "C" at -144.57,-3310.05 h80
  text "2017" at -344.57,-3316.05 h100
  text "SILICON LABS" at -843.57,-3469.05 h100
Mechanical 30:
  lines w7.87: 1361.21,-2483.05 1361.21,-1662.58 6085.62,-1662.58 ; 1361.21,-2328.09 2936.01,-2328.09 ; 1361.21,-2170.61 2936.01,-2170.61 6085.62,-2170.65 ; 1361.21,-2013.13 2936.01,-2013.13 ; 2936.01,-1855.65 6085.62,-1855.65 ; 2936.28,-2483.05 2936.28,-1662.58 ; 2936.28,-1662.18 2936.28,-1377.95 6087.58,-1377.95
  text "EFR32FG14 Discrete Balun 434/915MHz 20dBm" at 2992.13,-1496.06 h70.87
  text "CUSTOMER" at 2979.65,-1738.05 h50
  text "PROJECT NO" at 1419.65,-1778.05 h60
  text "SILICON LABS" at 3666.34,-1811.02 h98.43
  text "DRAWING TITLE" at 2988.65,-1932.05 h60
  text "xxxx" at 1419.4,-1938.98 h82.68
  text "DATE" at 1419.65,-2098.05 h60
  text "EFR32 Sub-GHz Discrete Balun Reference" at 2985.24,-2099.41 h70.87
  text "'.Print_Date'" at 2139.65,-2138.05 h60
  text "SHEET NAME" at 2980.65,-2253.05 h60
  text "DRAWN" at 1419.65,-2258.05 h60
  text "CHECK" at 1419.65,-2418.05 h60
